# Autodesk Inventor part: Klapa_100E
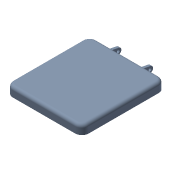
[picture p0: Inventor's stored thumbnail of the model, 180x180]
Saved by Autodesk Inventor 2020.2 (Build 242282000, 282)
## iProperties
Created: 2005-10
Part Number: Klapa_100E
Document SubType Name: Modeling
Designer: F.Stasiak
Density: 1 g/cm^3
Material: Ogólny
Appearance: Stalowoniebieska - jasna
Manager: www.cadconsulting.pl
Company: Fabian Stasiak CAD Consulting
Author: F.Stasiak
Subject: Zbiór ćwiczeń. Autodesk Inventor 2020. Kurs podstawowy
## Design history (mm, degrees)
sketch "Szkic1"
  geometry: L1 (-102.5, 114.834)-(102.5, 114.834) reference; L2 (-112.5, -125.166)-(-112.5, 104.834) reference; L3 (112.5, 104.834)-(112.5, -125.166) reference; L4 (102.5, -135.166)-(-102.5, -135.166) reference; L5 (124.5, -125.166)-(124.5, 104.834); L6 (102.5, 126.834)-(-102.5, 126.834); L7 (-124.5, 104.834)-(-124.5, -125.166); L8 (-102.5, -147.166)-(102.5, -147.166); A1 r 10 centre (-102.5, 104.834) between (-102.5, 114.834) and (-112.5, 104.834) reference; A2 r 10 centre (102.5, 104.834) between (112.5, 104.834) and (102.5, 114.834) reference; A3 r 10 centre (102.5, -125.166) between (102.5, -135.166) and (112.5, -125.166) reference; A4 r 10 centre (-102.5, -125.166) between (-112.5, -125.166) and (-102.5, -135.166) reference; A5 r 22 centre (102.5, 104.834) between (124.5, 104.834) and (102.5, 126.834); A6 r 22 centre (-102.5, 104.834) between (-102.5, 126.834) and (-124.5, 104.834); A7 r 22 centre (-102.5, -125.166) between (-124.5, -125.166) and (-102.5, -147.166); A8 r 22 centre (102.5, -125.166) between (102.5, -147.166) and (124.5, -125.166)
  constraints: 8 end point, 8 point on circle, 4 centre point, 7 other
  dimensions: "d0" = 12 distance between parallel lines of L2 L7
extrude "Wyciągnięcie proste1" new body sketch "Szkic1" distance "d1" = 30; taper "d2" = 0 deg
fillet "Zaokrąglenie1" dims "d3" = 10
feature "Skorupa1" dims "d4" = 2
node "Płaszczyzna konstrukcyjna1"
sketch "Szkic2"
  geometry: L1 (18, 9.299)-(18, -10.701) reference; L2 (18, 9.299)-(-1.073, 7.242); L3 (20.019, -16.725)-(-1.885, -12.522); C1 r 5 at (0, -2.701); A1 r 10 centre (0, -2.701) between (-1.073, 7.242) and (-1.885, -12.522); A2 r 10 centre (28, -10.701) between (18, -10.701) and (28, -20.701) reference
  constraints: 4 end point, 3 point on circle, 2 centre point, 2 tangent, 1 coincident
  dimensions: "d5" = 20 diameter of A1; "d14" = 10 diameter of C1
extrude "Wyciągnięcie proste2" join sketch "Szkic2" distance "d6" = 8; taper "d7" = 0 deg
mirror "Lustro1"
sketch "Szkic3"
  geometry: L1 (-137.166, 30)-(116.834, 30) reference; L2 (126.834, 20)-(126.834, 0) reference; L3 (126.834, 0)-(118.834, 0) reference; L4 (118.834, 0)-(118.834, 20) reference; L5 (116.834, 22)-(-137.166, 22) reference; L6 (-139.166, 20)-(-139.166, 0) reference; L7 (-139.166, 0)-(-147.166, 0) reference; L8 (-147.166, 0)-(-147.166, 20) reference; L9 (70.834, 22)-(70.834, -28); L10 (86.834, -28)-(86.834, 22); C1 r 5 at (78.834, -28); A1 r 10 centre (-137.166, 20) between (-137.166, 30) and (-147.166, 20) reference; A2 r 10 centre (116.834, 20) between (126.834, 20) and (116.834, 30) reference; A3 r 2 centre (116.834, 20) between (118.834, 20) and (116.834, 22) reference; A4 r 2 centre (-137.166, 20) between (-137.166, 22) and (-139.166, 20) reference; A5 r 8 centre (78.834, -28) between (70.834, -28) and (86.834, -28)
  constraints: 20 end point, 10 point on circle, 6 centre point, 4 horizontal, 4 vertical, 2 parallel, 2 point on line, 2 tangent, 1 coincident, 20 other
  dimensions: "d8" = 8 radius of A5; "d9" = 50 distance of L9.start L9.end; "d10" = 40 distance from line of L4 A5.centre; "d11" = 10 diameter of C1
extrude "Wyciągnięcie proste3" join sketch "Szkic3" stored distance "d12" = 8; taper "d13" = 0 deg
node "Bryła1"
node "Korpusy bryłowe"
node "Korpusy powierzchniowe"
node "Odniesienie1"
node "Odniesienie2"
node "Odniesienie3"
node "Odniesienie4"
node "Odniesienie5"
node "Odniesienie6"
node "Odniesienie7"
node "Odniesienie8"
